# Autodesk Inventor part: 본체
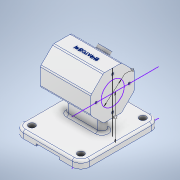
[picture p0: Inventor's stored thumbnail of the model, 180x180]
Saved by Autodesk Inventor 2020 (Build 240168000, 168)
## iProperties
Created: 2022-10
Part Number: 본체
Material: 알루미늄 6061
Document SubType Name: Modeling
Designer: 101-13
Mass: 558.501 g
Surface Area: 569.155 cm^2
Volume: 206.852 cm^3
Density: 2.7 g/cm^3
Appearance: 알루미늄 - 평지
Author: 101-13
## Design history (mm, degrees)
sketch "스케치1"
  geometry: L1 (46, -55)-(-46, -55); L2 (-46, -55)-(-46, 55); L3 (-46, 55)-(46, 55); L4 (46, 55)-(46, -55); L5 (46, -55)-(-46, 55); L6 (-46, -55)-(46, 55); 1 further point
  constraints: 12 end point, 2 midpoint, 2 parallel, 1 horizontal, 1 perpendicular
  dimensions: "d0" = 92 distance of L2.end L3.end; "d1" = 110 distance of L1.end L2.end
extrude "돌출1" new body sketch "스케치1" distance "d2" = 10; taper "d3" = 0 deg
fillet "모깎기1" dims "d4" = 12
node "작업 평면2"
sketch "스케치2"
  geometry: L1 (0, 0)-(86, 0) reference; L2 (-12, 10)-(-12, 0) reference; L3 (43, 62)-(43, 32); L4 (30.574, 92)-(55.426, 92); L5 (73, 74.426)-(73, 49.574); L6 (55.426, 32)-(30.574, 32); L7 (13, 49.574)-(13, 74.426); L8 (13, 92)-(73, 32); L9 (73, 92)-(13, 32); L10 (55.426, 32)-(73, 49.574); L11 (73, 74.426)-(55.426, 92); L12 (30.574, 92)-(13, 74.426); L13 (13, 49.574)-(30.574, 32); L14 (43, 19.574)-(43, 104.426); L15 (0, 62)-(0.574, 62); L16 (0, 0)-(-12, 0) reference; L17 (-12, 0)-(100.253, 0); L18 (-12, 62)-(100.253, 62); C1 r 30 at (43, 62)
  constraints: 30 end point, 7 parallel, 4 midpoint, 2 horizontal, 2 perpendicular, 1 centre point, 1 coincident
  dimensions: "d10" = 55 distance between parallel lines of L2 L3; "d12" = 60 distance of L8.end L9.end; "d82" = 62 distance between parallel lines of L17 L18
extrude "돌출2" join sketch "스케치2" stored distance "d14" = 70; taper "d15" = 0 deg
sketch "스케치9"
  geometry: L1 (20, 0)-(-20, 0); L2 (20, -6)-(-20, -6); L3 (-20, 6)-(20, 6); A1 r 6 centre (20, 0) between (20, -6) and (20, 6); A2 r 6 centre (-20, 0) between (-20, 6) and (-20, -6); 1 further point
  constraints: 8 end point, 4 point on circle, 4 tangent, 2 centre point, 1 midpoint, 1 parallel
extrude "돌출8" join sketch "스케치9" stored distance "d39" = 12; taper "d40" = 0 deg
sketch "스케치10"
  geometry: L1 (55.426, 92)-(30.574, 92) reference; L2 (43, 92)-(43, 32); L3 (55.426, 32)-(30.574, 32) reference; L4 (13, 74.426)-(13, 49.574) reference; L5 (73, 74.426)-(73, 49.574) reference; L6 (13, 62)-(73, 62); 6 further points
  constraints: 4 end point, 4 midpoint, 4 point on line
hole "구멍1" sketch "스케치10" at (43, 84.818), (20.001, 62), (43, 38.818), (65.999, 62) diameter "d42" = 3.242; stored, may be unused: countersink angle "d46" = 90 deg, drill point angle "d48" = 118 deg; dims "d43" = 8, "d44" = 4, "d45" = 2, "d47" = 10
sketch "스케치11"
  geometry: L1 (70, 0)-(70, -24.853) reference; L2 (35, 0)-(35, -24.853); L3 (0, -24.853)-(0, 0) reference; L4 (0, -12.426)-(70, -12.426); C1 r 8 at (35, -12.426); 1 further point
  constraints: 4 end point, 3 midpoint, 1 centre point, 1 parallel
  dimensions: "d49" = 35 distance between parallel lines of L1 L2; "d50" = 16 diameter of C1
extrude "돌출9" join sketch "스케치11" distance "d51" = 5; taper "d52" = 0 deg
sketch "스케치12"
  geometry: C1 r 4 at (0, 0); 1 further point
  constraints: 1 centre point
  dimensions: "d53" = 8 diameter of C1
extrude "돌출10" cut sketch "스케치12" distance "d54" = 30; taper "d55" = 0 deg
fillet "모깎기2" dims "d56" = 1
fillet "모깎기3" dims "d57" = 3
fillet "모깎기4" dims "d58" = 3
sketch "스케치13"
  geometry: L1 (18, 3)-(50, 3); L2 (50, 3)-(50, -3); L3 (50, -3)-(18, -3); L4 (18, -3)-(18, 3); L5 (18, 3)-(50, -3); L6 (50, 3)-(18, -3); 1 further point
  constraints: 12 end point, 2 midpoint, 2 parallel, 1 horizontal, 1 perpendicular
  dimensions: "d67" = 32 distance of L2.end L3.end; "d68" = 6 distance of L1.end L2.end
extrude "돌출11" cut sketch "스케치13" extent not by distance; stored distance "d69" = 0; taper "d70" = 0 deg
sketch "스케치14"
  geometry: C1 r 4.5 at (-34, -43); C2 r 4.5 at (34, -43); C3 r 4.5 at (34, 43); C4 r 4.5 at (-34, 43); A1 r 12 centre (-34, -43) between (-46, -43) and (-34, -55) reference; A2 r 12 centre (34, -43) between (34, -55) and (46, -43) reference; A3 r 12 centre (34, 43) between (46, 43) and (34, 55) reference; A4 r 12 centre (-34, 43) between (-34, 55) and (-46, 43) reference; 1 further point
  constraints: 4 centre point, 4 coincident
  dimensions: "d71" = 9 diameter of C1; "d72" = 9 diameter of C2; "d73" = 9 diameter of C3; "d74" = 9 diameter of C4
extrude "돌출12" cut sketch "스케치14" extent not by distance; stored distance "d75" = 0; taper "d76" = 0 deg
sketch "스케치15"
  geometry: L1 (51.159, 8.127)-(17.976, 8.127); L2 (17.976, 8.127)-(17.976, 12.93); L3 (17.976, 12.93)-(51.159, 12.93); L4 (51.159, 12.93)-(51.159, 8.127); 3 further points
  constraints: 1 coincident, 2 other
feature "엠보싱1" sketch "스케치15" dims "d0" = 92, "d1" = 110, "d77" = 0.5, "d78" = 0
fillet "모깎기7" dims "d79" = 3
sketch "스케치16"
  geometry: 1 further point
sketch "스케치17"
  geometry: L1 (-13.53, 0)-(106.864, 0); L2 (-13.53, 62)-(106.864, 62); L3 (43, 91.79)-(43, 0); C1 r 16 at (43, 62)
  constraints: 6 end point, 2 point on line, 1 centre point, 1 horizontal, 1 parallel, 1 vertical
  dimensions: "d80" = 62 distance between parallel lines of L1 L2; "d84" = 32 diameter of C1
node "솔리드1"
mirror "미러1"
feature "A9D066F2-1C7D-4E18-AEED-F7BC21143FA4" dims "d42" = 3.242, "d43" = 8, "d44" = 4, "d45" = 2, "d46" = 90 deg, "d47" = 10, "d48" = 118 deg
other parameters: "d9" = 62
